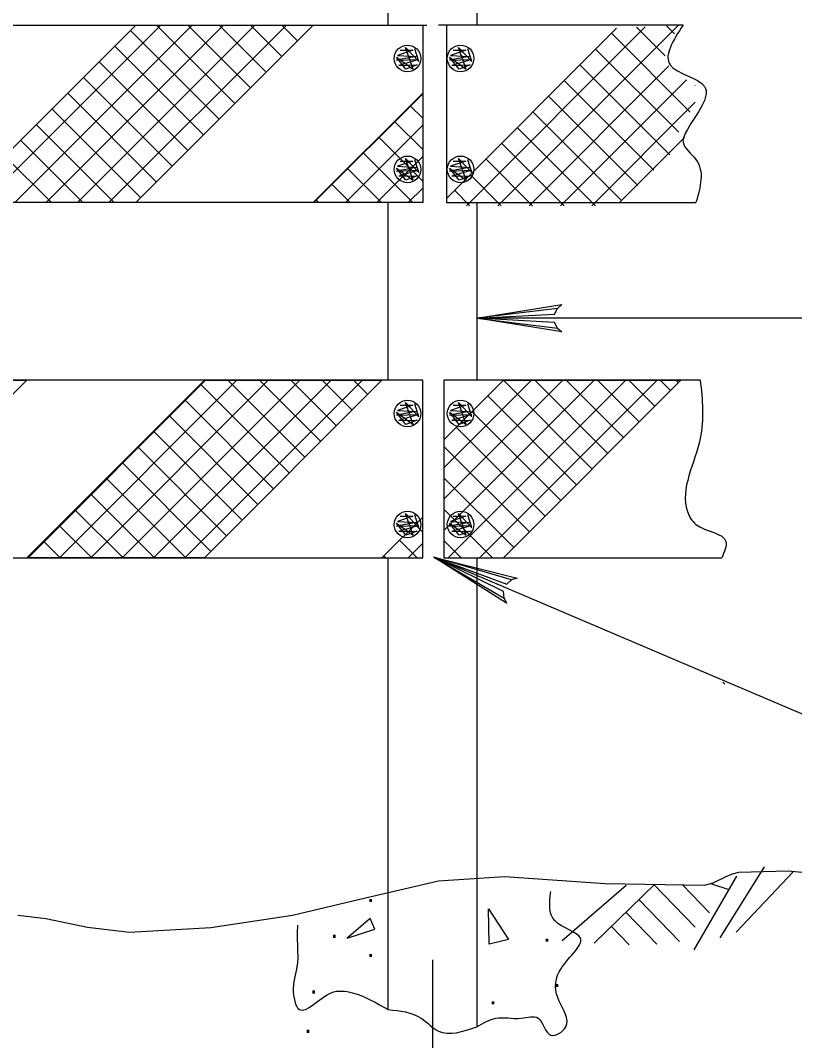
# Model space of a CAD drawing. Extents: x -4 to 901, y -468 to 720.
# Drawn here: x 220.5 to 262.4, y -334.3 to -279.2 of the extents above; entities that cross this region are included whole.
import ezdxf

# ---------------------------------------------------------------- set-up
doc = ezdxf.new("R2010")
doc.units = 0
doc.layers.add('2', color=7, linetype='Continuous')

msp = doc.modelspace()

# ---------------------------------------------------------------- linework, layer by layer
at = {"layer": '2'}
for p, q in [((240.37575, -279.407625), (240.37575, -269.807625)), ((245.17575, -272.235125), (245.17575, -279.407625)), ((110.77575, -279.407625), (242.46375, -279.407625)), ((217.12375, -289.007625), (226.72375, -279.407625)), ((226.72375, -289.007625), (236.32375, -279.407625)), ((240.37575, -279.407625), (242.46375, -279.407625)), ((242.2415, -279.407625), (242.2415, -289.007625)), ((256.31975, -279.407625), (243.08975, -279.407625)), ((243.5185, -279.407625), (243.5185, -289.007625)), ((243.5185, -288.776875), (252.72175, -279.573625)), ((241.71575, -281.791625), (241.30375, -280.611625)), ((241.30375, -280.611625), (242.02375, -281.381625)), ((242.02375, -281.381625), (241.80775, -280.683625)), ((244.58375, -281.791625), (244.17375, -280.611625)), ((244.17375, -280.611625), (244.89375, -281.381625)), ((244.89375, -281.381625), (244.67775, -280.683625)), ((241.88775, -281.099625), (240.82175, -281.301625)), ((241.33375, -281.791625), (240.82175, -281.135625)), ((240.82175, -281.135625), (241.71575, -281.791625)), ((240.82175, -281.301625), (242.00975, -281.259625)), ((241.69975, -280.761625), (240.87175, -281.043625)), ((240.87175, -281.043625), (241.88775, -281.099625)), ((242.00975, -281.259625), (240.95175, -281.583625)), ((241.02375, -280.761625), (241.69975, -280.761625)), ((241.41975, -281.207625), (241.41975, -281.207625)), ((241.41975, -281.207625), (241.41975, -281.207625)), ((241.88975, -281.207625), (241.88975, -281.207625)), ((244.75775, -281.099625), (243.69175, -281.301625)), ((244.20375, -281.791625), (243.69175, -281.135625)), ((243.69175, -281.135625), (244.58375, -281.791625)), ((243.69175, -281.301625), (244.87975, -281.259625)), ((244.56975, -280.761625), (243.74175, -281.043625)), ((243.74175, -281.043625), (244.75775, -281.099625)), ((244.87975, -281.259625), (243.82175, -281.583625)), ((243.89375, -280.761625), (244.56975, -280.761625)), ((244.28975, -281.207625), (244.28975, -281.207625)), ((244.28975, -281.207625), (244.28975, -281.207625)), ((240.95175, -281.583625), (241.93175, -281.561625)), ((241.93175, -281.561625), (241.33375, -281.791625)), ((243.82175, -281.583625), (244.79975, -281.561625)), ((244.79975, -281.561625), (244.20375, -281.791625)), ((236.32375, -289.007625), (242.2415, -283.089875)), ((252.88775, -289.007625), (256.40575, -285.489625)), ((241.69975, -286.761625), (240.87175, -287.043625)), ((241.02375, -286.761625), (241.69975, -286.761625)), ((241.71575, -287.791625), (241.30375, -286.611625)), ((241.30375, -286.611625), (242.02375, -287.381625)), ((242.02375, -287.381625), (241.80775, -286.683625)), ((244.56975, -286.761625), (243.74175, -287.043625)), ((243.89375, -286.761625), (244.56975, -286.761625)), ((244.58375, -287.791625), (244.17375, -286.611625)), ((244.17375, -286.611625), (244.89375, -287.381625)), ((244.89375, -287.381625), (244.67775, -286.683625)), ((241.88775, -287.099625), (240.82175, -287.301625)), ((241.33375, -287.791625), (240.82175, -287.135625)), ((240.82175, -287.135625), (241.71575, -287.791625)), ((240.82175, -287.301625), (242.00975, -287.259625)), ((240.87175, -287.043625), (241.88775, -287.099625)), ((242.00975, -287.259625), (240.95175, -287.583625)), ((241.41975, -287.207625), (241.41975, -287.207625)), ((241.41975, -287.207625), (241.41975, -287.207625)), ((244.75775, -287.099625), (243.69175, -287.301625)), ((244.20375, -287.791625), (243.69175, -287.135625)), ((243.69175, -287.135625), (244.58375, -287.791625)), ((243.69175, -287.301625), (244.87975, -287.259625)), ((243.74175, -287.043625), (244.75775, -287.099625)), ((244.87975, -287.259625), (243.82175, -287.583625)), ((244.28975, -287.207625), (244.28975, -287.207625)), ((240.95175, -287.583625), (241.93175, -287.561625)), ((241.93175, -287.561625), (241.33375, -287.791625)), ((243.82175, -287.583625), (244.79975, -287.561625)), ((244.79975, -287.561625), (244.20375, -287.791625)), ((242.2415, -289.007625), (110.77575, -289.007625)), ((243.5185, -289.007625), (257.01775, -289.007625)), ((242.2415, -298.607625), (110.77575, -298.607625)), ((211.23775, -308.207625), (220.83775, -298.607625)), ((220.83775, -308.207625), (230.43775, -298.607625)), ((230.43775, -308.207625), (240.03775, -298.607625)), ((242.2415, -308.207625), (242.2415, -298.607625)), ((243.39075, -301.820625), (246.60375, -298.607625)), ((257.24975, -298.607625), (243.39075, -298.607625)), ((243.39075, -298.607625), (243.39075, -308.207625)), ((246.60375, -308.207625), (256.20375, -298.607625)), ((246.60375, -298.607625), (256.20375, -298.607625)), ((256.20375, -298.607625), (246.60375, -308.207625)), ((241.69975, -299.961625), (240.87175, -300.243625)), ((241.02375, -299.961625), (241.69975, -299.961625)), ((241.71575, -300.991625), (241.30375, -299.811625)), ((241.30375, -299.811625), (242.02375, -300.581625)), ((242.02375, -300.581625), (241.80775, -299.883625)), ((244.56975, -299.961625), (243.74175, -300.243625)), ((243.89375, -299.961625), (244.56975, -299.961625)), ((244.58375, -300.991625), (244.17375, -299.811625)), ((244.17375, -299.811625), (244.89375, -300.581625)), ((244.89375, -300.581625), (244.67775, -299.883625)), ((241.88775, -300.299625), (240.82175, -300.501625)), ((241.33375, -300.991625), (240.82175, -300.335625)), ((240.82175, -300.335625), (241.71575, -300.991625)), ((240.82175, -300.501625), (242.00975, -300.459625)), ((240.87175, -300.243625), (241.88775, -300.299625)), ((242.00975, -300.459625), (240.95175, -300.783625)), ((241.41975, -300.407625), (241.41975, -300.407625)), ((241.41975, -300.407625), (241.41975, -300.407625)), ((244.75775, -300.299625), (243.69175, -300.501625)), ((244.20375, -300.991625), (243.69175, -300.335625)), ((243.69175, -300.335625), (244.58375, -300.991625)), ((243.69175, -300.501625), (244.87975, -300.459625)), ((243.74175, -300.243625), (244.75775, -300.299625)), ((244.87975, -300.459625), (243.82175, -300.783625)), ((244.28975, -300.407625), (244.28975, -300.407625)), ((240.95175, -300.783625), (241.93175, -300.761625)), ((241.93175, -300.761625), (241.33375, -300.991625)), ((243.82175, -300.783625), (244.79975, -300.761625)), ((244.79975, -300.761625), (244.20375, -300.991625)), ((240.03775, -308.207625), (242.2415, -306.003875)), ((241.69975, -305.961625), (240.87175, -306.243625)), ((241.02375, -305.961625), (241.69975, -305.961625)), ((241.71575, -306.991625), (241.30375, -305.811625)), ((241.30375, -305.811625), (242.02375, -306.581625)), ((242.02375, -306.581625), (241.80775, -305.883625)), ((244.56975, -305.961625), (243.74175, -306.243625)), ((243.89375, -305.961625), (244.56975, -305.961625)), ((244.58375, -306.991625), (244.17375, -305.811625)), ((244.17375, -305.811625), (244.89375, -306.581625)), ((244.89375, -306.581625), (244.67775, -305.883625)), ((241.88775, -306.299625), (240.82175, -306.501625)), ((241.33375, -306.991625), (240.82175, -306.335625)), ((240.82175, -306.335625), (241.71575, -306.991625)), ((240.82175, -306.501625), (242.00975, -306.459625)), ((240.87175, -306.243625), (241.88775, -306.299625)), ((242.00975, -306.459625), (240.95175, -306.783625)), ((241.41975, -306.407625), (241.41975, -306.407625)), ((241.41975, -306.407625), (241.41975, -306.407625)), ((244.75775, -306.299625), (243.69175, -306.501625)), ((244.20375, -306.991625), (243.69175, -306.335625)), ((243.69175, -306.335625), (244.58375, -306.991625)), ((243.69175, -306.501625), (244.87975, -306.459625)), ((243.74175, -306.243625), (244.75775, -306.299625)), ((244.87975, -306.459625), (243.82175, -306.783625)), ((244.28975, -306.407625), (244.28975, -306.407625)), ((240.95175, -306.783625), (241.93175, -306.761625)), ((241.93175, -306.761625), (241.33375, -306.991625)), ((243.82175, -306.783625), (244.79975, -306.761625)), ((244.79975, -306.761625), (244.20375, -306.991625)), ((110.77575, -308.207625), (242.2415, -308.207625)), ((243.39075, -308.207625), (258.40975, -308.207625)), ((258.31975, -328.755625), (260.71775, -324.921625)), ((259.18775, -328.441625), (262.29975, -325.161625)), ((249.78975, -328.891625), (253.24175, -325.897625)), ((251.51775, -329.039625), (254.79975, -325.859625)), ((254.72975, -325.857625), (256.97375, -328.173625)), ((256.28375, -325.881625), (257.74775, -327.391625)), ((256.92975, -329.395625), (259.22575, -325.415625)), ((257.85175, -325.825625), (258.80175, -326.147625)), ((253.93975, -326.693625), (256.13375, -328.955625)), ((253.23775, -327.373625), (254.90375, -329.093625)), ((252.44775, -328.137625), (253.39975, -329.121625)), ((242.77575, -329.945625), (242.77575, -358.167625))]:
    msp.add_line(p, q, dxfattribs=at)
for points in [[(217.12375, -289.007625), (226.72375, -279.407625), (236.32375, -279.407625), (226.72375, -289.007625)], [(201.63775, -308.207625), (211.23775, -298.607625), (220.83775, -298.607625), (211.23775, -308.207625)], [(220.83775, -308.207625), (230.43775, -298.607625), (240.03775, -298.607625), (230.43775, -308.207625)], [(246.88375, -328.847625), (245.83975, -329.087625), (245.80375, -327.179625)], [(239.64975, -328.275625), (239.39775, -327.699625), (238.16175, -328.767625)]]:
    msp.add_lwpolyline(points, close=True, dxfattribs=at)
for points in [[(218.47775, -289.007625), (228.07775, -279.407625)], [(220.17375, -289.007625), (229.77375, -279.407625)], [(221.87175, -289.007625), (231.47175, -279.407625)], [(223.56775, -289.007625), (233.16775, -279.407625)], [(225.26575, -289.007625), (234.86575, -279.407625)], [(232.08175, -283.649625), (227.84175, -279.407625)], [(232.93175, -282.801625), (229.53975, -279.407625)], [(233.77975, -281.951625), (231.23575, -279.407625)], [(234.62775, -281.103625), (232.93375, -279.407625)], [(235.47575, -280.255625), (234.62975, -279.407625)], [(244.59975, -289.173625), (254.27175, -279.503625)], [(246.29775, -289.173625), (256.04975, -279.421625)], [(255.34575, -281.061625), (253.80975, -279.523625)], [(255.86575, -279.881625), (255.43175, -279.449625)], [(256.28175, -279.449625), (256.24375, -279.411625)], [(231.23375, -284.497625), (226.43375, -279.697625)], [(256.70975, -284.121625), (252.44175, -279.853625)], [(230.38575, -285.345625), (225.58575, -280.545625)], [(256.09775, -285.205625), (251.59375, -280.701625)], [(229.53775, -286.195625), (224.73775, -281.395625)], [(247.99375, -289.173625), (255.55775, -281.609625)], [(255.61175, -286.417625), (250.74575, -281.549625)], [(228.68775, -287.043625), (223.88775, -282.243625)], [(249.69175, -289.173625), (256.49975, -282.365625)], [(254.74375, -287.245625), (249.89575, -282.399625)], [(256.97975, -282.695625), (256.95175, -282.665625)], [(227.83975, -287.891625), (223.03975, -283.091625)], [(236.35775, -289.007625), (242.2415, -283.123875)], [(253.87375, -288.073625), (249.04775, -283.247625)], [(226.99175, -288.739625), (222.19175, -283.939625)], [(242.2415, -284.445375), (241.56375, -283.767625)], [(251.38775, -289.173625), (256.97975, -283.581625)], [(253.00575, -288.903625), (248.19975, -284.095625)], [(225.56175, -289.007625), (221.34375, -284.789625)], [(238.05575, -289.007625), (242.2415, -284.821875)], [(242.2415, -286.141375), (240.71575, -284.615625)], [(251.57975, -289.173625), (247.34975, -284.945625)], [(223.86575, -289.007625), (220.49375, -285.637625)], [(242.2415, -287.839125), (239.86775, -285.463625)], [(249.88375, -289.173625), (246.50175, -285.793625)], [(222.16775, -289.007625), (219.64575, -286.485625)], [(241.71375, -289.007625), (239.01975, -286.313625)], [(239.75175, -289.007625), (242.2415, -286.517875)], [(248.18575, -289.173625), (245.65375, -286.641625)], [(240.01775, -289.007625), (238.16975, -287.161625)], [(246.48975, -289.173625), (244.80575, -287.489625)], [(238.31975, -289.007625), (237.32175, -288.009625)], [(241.44975, -289.007625), (242.2415, -288.215875)], [(244.79175, -289.173625), (243.95575, -288.339625)], [(236.62375, -289.007625), (236.47375, -288.857625)], [(240.37575, -298.607625), (240.37575, -289.007625)], [(245.17575, -289.007625), (245.17575, -298.607625)], [(249.53575, -295.797625), (249.37175, -295.481625), (245.17575, -295.249625), (249.53575, -295.797625), (249.75775, -295.987625), (245.17575, -295.249625), (249.36975, -295.041625), (249.52175, -294.729625), (245.17575, -295.249625), (249.75775, -294.521625), (249.52175, -294.729625)], [(269.09375, -295.249625), (257.09375, -295.249625), (245.17575, -295.249625)], [(220.89575, -308.207625), (230.49575, -298.607625)], [(222.59375, -308.207625), (232.19375, -298.607625)], [(224.28975, -308.207625), (233.88975, -298.607625)], [(225.98775, -308.207625), (235.58775, -298.607625)], [(227.68375, -308.207625), (237.28375, -298.607625)], [(229.38175, -308.207625), (238.98175, -298.607625)], [(235.02375, -303.621625), (230.22375, -298.821625)], [(235.87175, -302.773625), (231.70775, -298.607625)], [(236.72175, -301.923625), (233.40575, -298.607625)], [(237.56975, -301.075625), (235.10175, -298.607625)], [(238.41775, -300.227625), (236.79975, -298.607625)], [(239.26775, -299.379625), (238.49575, -298.607625)], [(243.39075, -306.738625), (251.51975, -298.607625)], [(243.39075, -305.040625), (249.82375, -298.607625)], [(243.39075, -303.344625), (248.12575, -298.607625)], [(243.61775, -308.207625), (253.21775, -298.607625)], [(245.31575, -308.207625), (254.91375, -298.607625)], [(251.40375, -303.407625), (246.60375, -298.607625), (246.60375, -298.607625)], [(252.25175, -302.559625), (248.30175, -298.607625)], [(253.09975, -301.711625), (249.99775, -298.607625)], [(253.94975, -300.863625), (251.69575, -298.607625)], [(254.79775, -300.013625), (253.39175, -298.607625)], [(255.64575, -299.165625), (255.08975, -298.607625)], [(256.06975, -298.741625), (255.93775, -298.607625)], [(250.55575, -304.257625), (245.75575, -299.457625)], [(234.17575, -304.469625), (229.37575, -299.669625)], [(233.32775, -305.317625), (228.52775, -300.519625)], [(249.70575, -305.105625), (244.90575, -300.305625)], [(232.47775, -306.167625), (227.67775, -301.367625)], [(248.85775, -305.953625), (244.05775, -301.153625)], [(231.62975, -307.015625), (226.82975, -302.215625)], [(248.00975, -306.801625), (243.39075, -302.184625)], [(230.78175, -307.863625), (225.98175, -303.063625)], [(247.16175, -307.651625), (243.39075, -303.880625)], [(229.42775, -308.207625), (225.13375, -303.913625)], [(227.73175, -308.207625), (224.28375, -304.761625)], [(226.03375, -308.207625), (223.43575, -305.609625)], [(246.02175, -308.207625), (243.39075, -305.578375)], [(224.33775, -308.207625), (222.58775, -306.457625)], [(242.2415, -306.817375), (241.83575, -306.411625), (241.83575, -306.411625)], [(222.63975, -308.207625), (221.73975, -307.307625)], [(241.93575, -308.207625), (240.98575, -307.259625), (240.98575, -307.259625)], [(241.44975, -308.207625), (242.2415, -307.415875)], [(244.32375, -308.207625), (243.39075, -307.274625)], [(220.94375, -308.207625), (220.88975, -308.155625)], [(240.23775, -308.207625), (240.13775, -308.107625), (240.13775, -308.107625)], [(240.37575, -332.633625), (240.37575, -308.207625)], [(270.65975, -317.973625), (265.85975, -317.973625), (242.84375, -308.179625)], [(246.63975, -310.389625), (246.61375, -310.035625), (242.84375, -308.179625), (246.63975, -310.389625), (246.76975, -310.653625), (242.84375, -308.179625), (246.78175, -309.629625), (247.04575, -309.403625), (242.84375, -308.179625), (247.34375, -309.303625), (247.04575, -309.403625)], [(245.17575, -308.207625), (245.17575, -333.561625)], [(258.58575, -315.041625), (258.46575, -314.921625)], [(220.34175, -327.525625), (221.85375, -327.711625), (224.11375, -328.177625), (226.37575, -328.453625), (230.78575, -328.189625), (235.19775, -327.525625), (239.15375, -326.595625), (243.08975, -325.669625), (246.66375, -325.431625), (252.11175, -325.817625), (257.48175, -325.901625), (257.95575, -325.773625), (258.64575, -325.433625), (258.98975, -325.285625), (259.33775, -325.205625), (261.99975, -325.135625), (264.05375, -325.331625)], [(250.21775, -328.495625), (250.22175, -328.497625)], [(250.22175, -328.497625), (250.22175, -328.497625)]]:
    msp.add_lwpolyline(points, dxfattribs=at)
for centre in [(241.41989, -281.208528), (244.28957, -281.208528), (241.41989, -287.208528), (244.28957, -287.208528), (241.41989, -300.408528), (244.28957, -300.408528), (241.41989, -306.408528), (244.28957, -306.408528)]:
    msp.add_circle(centre, 0.72, dxfattribs=at)
for points in [[(256.31975, -279.407625), (255.62375, -281.563625), (257.48175, -282.725625), (256.55375, -285.045625), (256.31975, -285.743625), (257.01775, -286.671625), (257.01775, -289.007625)], [(257.24975, -298.607625), (257.24975, -301.759625), (256.55375, -305.705625), (257.01775, -306.401625), (258.64175, -307.331625), (258.40975, -308.207625)], [(245.17575, -333.561625), (246.19775, -333.093625), (247.56775, -333.093625), (248.48175, -333.093625), (249.16775, -334.007625), (249.97575, -333.561625), (249.62375, -332.179625), (249.62375, -330.581625), (250.76575, -328.753625), (249.39575, -327.839625), (249.16775, -326.241625)], [(235.46375, -328.069625), (235.46375, -329.209625), (235.46375, -330.123625), (235.23575, -331.493625), (235.57575, -332.633625), (237.29175, -331.723625), (238.43375, -331.723625), (240.37575, -332.633625)], [(240.37575, -332.633625), (242.16175, -333.097625), (243.08975, -333.793625), (245.17575, -333.561625)]]:
    msp.add_spline(points, degree=3, dxfattribs=at)

# ---------------------------------------------------------------- texts
for p in [(239.21775, -326.817625), (237.24975, -328.761625), (248.75775, -328.965625), (239.21775, -329.793625), (249.29775, -331.413625), (236.13375, -331.761625), (245.84175, -332.349625), (235.82175, -333.897625)]:
    msp.add_text('.', height=1.116, dxfattribs=at).set_placement(p)

doc.saveas('drawing.dxf')
